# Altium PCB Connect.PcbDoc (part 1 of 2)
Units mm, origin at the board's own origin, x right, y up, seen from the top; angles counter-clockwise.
Board outline 480 x 50 mm, 2 copper layers (Top Layer, Bottom Layer); 349 components, 200 nets, 1147 pads, 734 vias.
Unrouted connection lines stored in the file: 1.
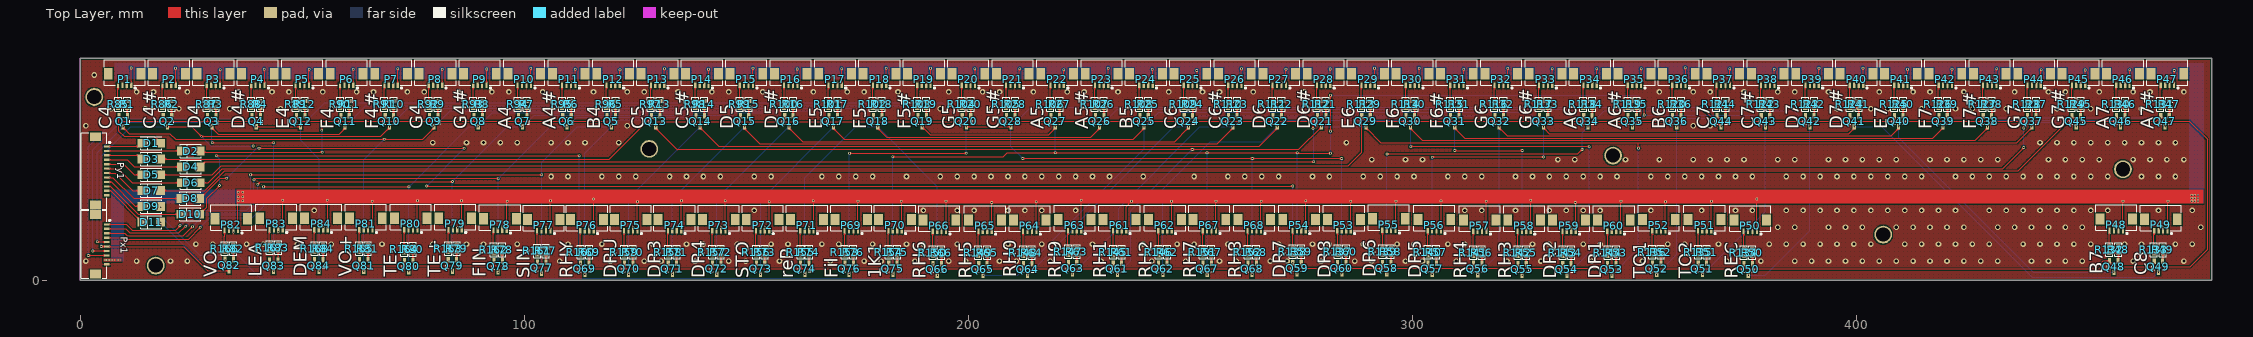
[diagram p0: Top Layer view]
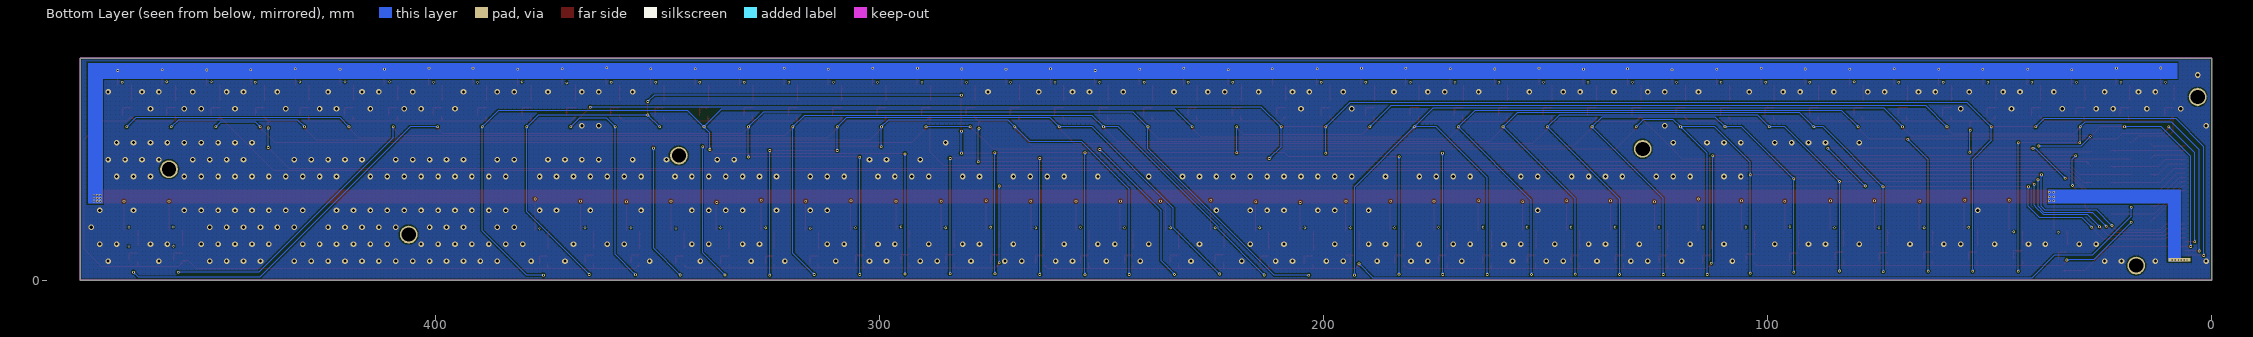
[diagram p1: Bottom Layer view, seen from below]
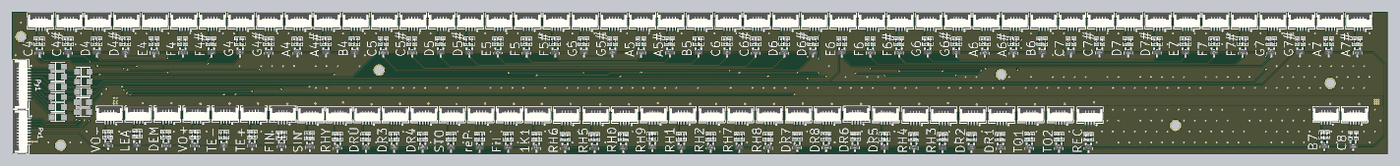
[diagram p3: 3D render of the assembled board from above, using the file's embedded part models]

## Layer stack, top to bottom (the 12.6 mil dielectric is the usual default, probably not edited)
Top Solder: solder mask 0.0102, Solder Resist, Dk 3.5
Top Layer: signal copper 0.0356
Dielectric 1: dielectric 0.32, FR-4, Dk 4.8
Bottom Layer: signal copper 0.0356
Bottom Solder: solder mask 0.0102, Solder Resist, Dk 3.5

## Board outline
0,0 0,50 480,50 480,0

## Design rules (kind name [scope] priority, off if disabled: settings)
Clearance [All] p1: gap=0.254
PolygonConnect [All] p1: connectstyle=Relief reliefconductorwidth=0.254 reliefentries=4 polygonreliefangle="90 Angle" airgapwidth=0.254
RoutingVias [All] p1: holewidth=0.3 width=0.6 viastyle="Through Hole" minholewidth=0.3 minwidth=0.6 maxholewidth=0.711 maxwidth=1.27
SolderMaskExpansion [All] p1: expansion=0.102
Width [All] p1: maxlimit=0.254 minlimit=0.254 preferedwidth=0.254
30 further rules are at their usual default settings.

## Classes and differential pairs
component class Sheet3: D1 D2 D3 D4 D5 D6 D7 D8 D9 D10 D11 Px1 Py1 Q1 Q2 Q3 Q4 Q5 Q6 Q7 Q8 Q9 Q10 Q11 Q12 Q13 Q14 Q15 Q16 Q17 Q18 Q19 Q20 Q21 Q22 Q23 Q24 Q25 Q26 Q27 Q28 Q29 Q30 Q31 Q32 Q33 Q34 Q35 Q36 Q37 Q38 Q39 Q40 Q41 Q42 Q43 Q44 Q45 Q46 Q47 Q48 Q49 Q50 Q51 Q52 Q53 Q54 Q55 Q56 Q57 Q58 Q59 Q60 Q61 Q62 Q63 Q64 Q65 Q66 Q67 Q68 Q69 Q70 Q71 Q72 Q73 Q74 Q75 Q76 Q77 Q79 Q80 Q81 Q82 Q83 Q84 R1 R2 R3 R4 R5 R6 R7 R8 R9 R10 R11 R12 R13 R14 R15 R16 R17 R18 R19 R20 R21 R22 R23 R24 R25 R26 R27 R28 R29 R30 R31 R32 R33 R34 R35 R36 R37 R38 R39 R40 R41 R42 R43 R44 R45 R46 R47 R48 R49 R50 R51 R52 R53 R54 R55 R56 R57 R58 R59 R60 R61 R62 R63 R64 R65 R66 R67 R68 R69 R70 R71 R72 R73 R74 R75 R76 R77 R79 R80 R81 R82 R83 R84
component class CONNECT: P21 P22 P23 P24 P25 P26 P27 P28 P29 P30 P31 P32 P33 P34 P35 P36 P37 P38 P39 P40 P41 P42 P43 P44 P45 P46 P47 P48 P49 P50 P51 P52 P53 P54 P55 P56 P57 P58 P59 P60 P61 P62 P63 P64 P65 P66 P67 P68 P69 P70 P71 P72 P73 P74 P75 P76 P77 P78 P79 P80 P81 P82 P83 P84 R105 R106 R107 R108 R109 R110 R111 R112 R113 R114 R115 R116 R117 R118 R119 R120 R121 R122 R123 R124 R125 R126 R127 R128 R129 R130 R131 R132 R133 R134 R135 R136 R137 R138 R139 R140 R141 R142 R143 R144 R145 R146 R147 R148 R149 R150 R151 R152 R153 R154 R155 R156 R157 R158 R159 R160 R161 R163 R164 R165 R166 R167 R168
component class CONNECT2: P1 P2 P3 P4 P5 P6 P7 P8 P9 P10 P11 P12 P13 P14 P15 P16 P17 P18 P19 P20 R85 R86 R87 R88 R89 R90 R91 R92 R93 R94 R95 R96 R97 R98 R99 R100 R101 R102 R103 R104

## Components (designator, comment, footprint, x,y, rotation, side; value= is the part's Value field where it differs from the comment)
D1 "M7" SMA(DO-214AC)_S1 16.002,30.861 r0 top
D2 "M7" SMA(DO-214AC)_S1 24.892,29.083 r0 top
D3 "M7" SMA(DO-214AC)_S1 16.002,27.305 r0 top
D4 "M7" SMA(DO-214AC)_S1 24.892,25.527 r0 top
D5 "M7" SMA(DO-214AC)_S1 16.002,23.749 r0 top
D6 "M7" SMA(DO-214AC)_S1 24.892,21.971 r0 top
D7 "M7" SMA(DO-214AC)_S1 16.002,20.193 r0 top
D8 "M7" SMA(DO-214AC)_S1 24.765,18.415 r0 top
D9 "M7" SMA(DO-214AC)_S1 16.002,16.637 r0 top
D10 "M7" SMA(DO-214AC)_S1 24.765,14.859 r0 top
D11 "M7" SMA(DO-214AC)_S1 16.002,13.081 r0 top
P1 "Header 4" FPC1.0-2H-WS-4P 10,46.5 r180 top
P2 "Header 4" FPC1.0-2H-WS-4P 20,46.5 r180 top
P3 "Header 4" FPC1.0-2H-WS-4P 30,46.5 r180 top
P4 "Header 4" FPC1.0-2H-WS-4P 40,46.5 r180 top
P5 "Header 4" FPC1.0-2H-WS-4P 50,46.5 r180 top
P6 "Header 4" FPC1.0-2H-WS-4P 60,46.5 r180 top
P7 "Header 4" FPC1.0-2H-WS-4P 70,46.5 r180 top
P8 "Header 4" FPC1.0-2H-WS-4P 80,46.5 r180 top
P9 "Header 4" FPC1.0-2H-WS-4P 90,46.5 r180 top
P10 "Header 4" FPC1.0-2H-WS-4P 100,46.5 r180 top
P11 "Header 4" FPC1.0-2H-WS-4P 110,46.5 r180 top
P12 "Header 4" FPC1.0-2H-WS-4P 120,46.5 r180 top
P13 "Header 4" FPC1.0-2H-WS-4P 130,46.5 r180 top
P14 "Header 4" FPC1.0-2H-WS-4P 140,46.5 r180 top
P15 "Header 4" FPC1.0-2H-WS-4P 150,46.5 r180 top
P16 "Header 4" FPC1.0-2H-WS-4P 160,46.5 r180 top
P17 "Header 4" FPC1.0-2H-WS-4P 170,46.5 r180 top
P18 "Header 4" FPC1.0-2H-WS-4P 180,46.5 r180 top
P19 "Header 4" FPC1.0-2H-WS-4P 190,46.5 r180 top
P20 "Header 4" FPC1.0-2H-WS-4P 200,46.5 r180 top
P21 "Header 4" FPC1.0-2H-WS-4P 210,46.5 r180 top
P22 "Header 4" FPC1.0-2H-WS-4P 220,46.5 r180 top
P23 "Header 4" FPC1.0-2H-WS-4P 230,46.5 r180 top
P24 "Header 4" FPC1.0-2H-WS-4P 240,46.5 r180 top
P25 "Header 4" FPC1.0-2H-WS-4P 250,46.5 r180 top
P26 "Header 4" FPC1.0-2H-WS-4P 260,46.5 r180 top
P27 "Header 4" FPC1.0-2H-WS-4P 270,46.5 r180 top
P28 "Header 4" FPC1.0-2H-WS-4P 280,46.5 r180 top
P29 "Header 4" FPC1.0-2H-WS-4P 290,46.5 r180 top
P30 "Header 4" FPC1.0-2H-WS-4P 300,46.5 r180 top
P31 "Header 4" FPC1.0-2H-WS-4P 310,46.5 r180 top
P32 "Header 4" FPC1.0-2H-WS-4P 320,46.5 r180 top
P33 "Header 4" FPC1.0-2H-WS-4P 330,46.5 r180 top
P34 "Header 4" FPC1.0-2H-WS-4P 340,46.5 r180 top
P35 "Header 4" FPC1.0-2H-WS-4P 350,46.5 r180 top
P36 "Header 4" FPC1.0-2H-WS-4P 360,46.5 r180 top
P37 "Header 4" FPC1.0-2H-WS-4P 370,46.5 r180 top
P38 "Header 4" FPC1.0-2H-WS-4P 380,46.5 r180 top
P39 "Header 4" FPC1.0-2H-WS-4P 390,46.5 r180 top
P40 "Header 4" FPC1.0-2H-WS-4P 400,46.5 r180 top
P41 "Header 4" FPC1.0-2H-WS-4P 410,46.5 r180 top
P42 "Header 4" FPC1.0-2H-WS-4P 420,46.5 r180 top
P43 "Header 4" FPC1.0-2H-WS-4P 430,46.5 r180 top
P44 "Header 4" FPC1.0-2H-WS-4P 440,46.5 r180 top
P45 "Header 4" FPC1.0-2H-WS-4P 450,46.5 r180 top
P46 "Header 4" FPC1.0-2H-WS-4P 460,46.5 r180 top
P47 "Header 4" FPC1.0-2H-WS-4P 470,46.5 r180 top
P48 "Header 4" FPC1.0-2H-WS-4P 458.494,13.777 r180 top
P49 "Header 4" FPC1.0-2H-WS-4P 468.537,13.734 r180 top
P50 "Header 4" FPC1.0-2H-WS-4P 376.081,13.589 r180 top
P51 "Header 4" FPC1.0-2H-WS-4P 365.777,13.716 r180 top
P52 "Header 4" FPC1.0-2H-WS-4P 355.481,13.716 r180 top
P53 "Header 4" FPC1.0-2H-WS-4P 284.586,13.716 r180 top
P54 "Header 4" FPC1.0-2H-WS-4P 274.476,13.716 r180 top
P55 "Header 4" FPC1.0-2H-WS-4P 294.695,13.843 r180 top
P56 "Header 4" FPC1.0-2H-WS-4P 304.932,13.716 r180 top
P57 "Header 4" FPC1.0-2H-WS-4P 315.169,13.589 r180 top
P58 "Header 4" FPC1.0-2H-WS-4P 325.152,13.589 r180 top
P59 "Header 4" FPC1.0-2H-WS-4P 335.261,13.589 r180 top
P60 "Header 4" FPC1.0-2H-WS-4P 345.371,13.589 r180 top
P61 "Header 4" FPC1.0-2H-WS-4P 234.037,13.716 r180 top
P62 "Header 4" FPC1.0-2H-WS-4P 244.274,13.716 r180 top
P63 "Header 4" FPC1.0-2H-WS-4P 223.928,13.716 r180 top
P64 "Header 4" FPC1.0-2H-WS-4P 213.818,13.589 r180 top
P65 "Header 4" FPC1.0-2H-WS-4P 203.754,13.589 r180 top
P66 "Header 4" FPC1.0-2H-WS-4P 193.472,13.589 r180 top
P67 "Header 4" FPC1.0-2H-WS-4P 254.257,13.716 r180 top
P68 "Header 4" FPC1.0-2H-WS-4P 264.366,13.716 r180 top
P69 "Header 4" FPC1.0-2H-WS-4P 173.633,13.716 r180 top
P70 "Header 4" FPC1.0-2H-WS-4P 183.489,13.716 r180 top
P71 "Header 4" FPC1.0-2H-WS-4P 163.651,13.716 r180 top
P72 "Header 4" FPC1.0-2H-WS-4P 153.668,13.716 r180 top
P73 "Header 4" FPC1.0-2H-WS-4P 143.812,13.716 r180 top
P74 "Header 4" FPC1.0-2H-WS-4P 133.83,13.716 r180 top
P75 "Header 4" FPC1.0-2H-WS-4P 123.974,13.716 r180 top
P76 "Header 4" FPC1.0-2H-WS-4P 114.118,13.716 r180 top
P77 "Header 4" FPC1.0-2H-WS-4P 104.39,13.716 r180 top
P78 "Header 4" FPC1.0-2H-WS-4P 94.534,13.843 r180 top
P79 "Header 4" FPC1.0-2H-WS-4P 84.424,13.97 r180 top
P80 "Header 4" FPC1.0-2H-WS-4P 74.442,13.97 r180 top
P81 "Header 4" FPC1.0-2H-WS-4P 64.332,13.97 r180 top
P82 "Header 4" FPC1.0-2H-WS-4P 34.003,13.843 r180 top
P83 "Header 4" FPC1.0-2H-WS-4P 44.113,13.97 r180 top
P84 "Header 4" FPC1.0-2H-WS-4P 54.222,13.97 r180 top
Px1 "Header 10" FPC1.0-2H-WS-10P 3.429,8.087 r270 top
Py1 "Header 12" FPC1.0-2H-WS-12P 3.429,24.638 r270 top
Q1 "SS8050 Y1" SOT-23(SOT-23-3) 9.652,35.814 r90 top
Q2 "SS8050 Y1" SOT-23(SOT-23-3) 19.648,35.814 r90 top
Q3 "SS8050 Y1" SOT-23(SOT-23-3) 29.644,35.814 r90 top
Q4 "SS8050 Y1" SOT-23(SOT-23-3) 39.64,35.814 r90 top
Q5 "SS8050 Y1" SOT-23(SOT-23-3) 119.608,35.814 r90 top
Q6 "SS8050 Y1" SOT-23(SOT-23-3) 109.612,35.814 r90 top
Q7 "SS8050 Y1" SOT-23(SOT-23-3) 99.616,35.814 r90 top
Q8 "SS8050 Y1" SOT-23(SOT-23-3) 89.62,35.814 r90 top
Q9 "SS8050 Y1" SOT-23(SOT-23-3) 79.624,35.814 r90 top
Q10 "SS8050 Y1" SOT-23(SOT-23-3) 69.628,35.814 r90 top
Q11 "SS8050 Y1" SOT-23(SOT-23-3) 59.632,35.814 r90 top
Q12 "SS8050 Y1" SOT-23(SOT-23-3) 49.636,35.814 r90 top
Q13 "SS8050 Y1" SOT-23(SOT-23-3) 129.603,35.814 r90 top
Q14 "SS8050 Y1" SOT-23(SOT-23-3) 139.599,35.814 r90 top
Q15 "SS8050 Y1" SOT-23(SOT-23-3) 149.595,35.814 r90 top
Q16 "SS8050 Y1" SOT-23(SOT-23-3) 159.591,35.814 r90 top
Q17 "SS8050 Y1" SOT-23(SOT-23-3) 169.587,35.814 r90 top
Q18 "SS8050 Y1" SOT-23(SOT-23-3) 179.583,35.814 r90 top
Q19 "SS8050 Y1" SOT-23(SOT-23-3) 189.579,35.814 r90 top
Q20 "SS8050 Y1" SOT-23(SOT-23-3) 199.575,35.814 r90 top
Q21 "SS8050 Y1" SOT-23(SOT-23-3) 279.543,35.814 r90 top
Q22 "SS8050 Y1" SOT-23(SOT-23-3) 269.547,35.814 r90 top
Q23 "SS8050 Y1" SOT-23(SOT-23-3) 259.551,35.814 r90 top
Q24 "SS8050 Y1" SOT-23(SOT-23-3) 249.555,35.814 r90 top
Q25 "SS8050 Y1" SOT-23(SOT-23-3) 239.559,35.814 r90 top
Q26 "SS8050 Y1" SOT-23(SOT-23-3) 229.563,35.814 r90 top
Q27 "SS8050 Y1" SOT-23(SOT-23-3) 219.567,35.814 r90 top
Q28 "SS8050 Y1" SOT-23(SOT-23-3) 209.571,35.814 r90 top
Q29 "SS8050 Y1" SOT-23(SOT-23-3) 289.539,35.814 r90 top
Q30 "SS8050 Y1" SOT-23(SOT-23-3) 299.535,35.814 r90 top
Q31 "SS8050 Y1" SOT-23(SOT-23-3) 309.531,35.814 r90 top
Q32 "SS8050 Y1" SOT-23(SOT-23-3) 319.527,35.814 r90 top
Q33 "SS8050 Y1" SOT-23(SOT-23-3) 329.523,35.814 r90 top
Q34 "SS8050 Y1" SOT-23(SOT-23-3) 339.519,35.814 r90 top
Q35 "SS8050 Y1" SOT-23(SOT-23-3) 349.515,35.814 r90 top
Q36 "SS8050 Y1" SOT-23(SOT-23-3) 359.51,35.814 r90 top
Q37 "SS8050 Y1" SOT-23(SOT-23-3) 439.478,35.814 r90 top
Q38 "SS8050 Y1" SOT-23(SOT-23-3) 429.482,35.814 r90 top
Q39 "SS8050 Y1" SOT-23(SOT-23-3) 419.486,35.814 r90 top
Q40 "SS8050 Y1" SOT-23(SOT-23-3) 409.49,35.814 r90 top
Q41 "SS8050 Y1" SOT-23(SOT-23-3) 399.494,35.814 r90 top
Q42 "SS8050 Y1" SOT-23(SOT-23-3) 389.498,35.814 r90 top
Q43 "SS8050 Y1" SOT-23(SOT-23-3) 379.502,35.814 r90 top
Q44 "SS8050 Y1" SOT-23(SOT-23-3) 369.506,35.814 r90 top
Q45 "SS8050 Y1" SOT-23(SOT-23-3) 449.474,35.814 r90 top
Q46 "SS8050 Y1" SOT-23(SOT-23-3) 459.47,35.814 r90 top
Q47 "SS8050 Y1" SOT-23(SOT-23-3) 469.466,35.814 r90 top
Q48 "SS8050 Y1" SOT-23(SOT-23-3) 457.956,3.091 r90 top
Q49 "SS8050 Y1" SOT-23(SOT-23-3) 467.995,3.048 r90 top
Q50 "SS8050 Y1" SOT-23(SOT-23-3) 375.614,2.433 r90 top
Q51 "SS8050 Y1" SOT-23(SOT-23-3) 365.31,2.56 r90 top
Q52 "SS8050 Y1" SOT-23(SOT-23-3) 355.013,2.56 r90 top
Q53 "SS8050 Y1" SOT-23(SOT-23-3) 344.903,2.433 r90 top
Q54 "SS8050 Y1" SOT-23(SOT-23-3) 334.793,2.433 r90 top
Q55 "SS8050 Y1" SOT-23(SOT-23-3) 324.683,2.433 r90 top
Q56 "SS8050 Y1" SOT-23(SOT-23-3) 314.706,2.54 r90 top
Q57 "SS8050 Y1" SOT-23(SOT-23-3) 304.463,2.56 r90 top
Q58 "SS8050 Y1" SOT-23(SOT-23-3) 294.226,2.687 r90 top
Q59 "SS8050 Y1" SOT-23(SOT-23-3) 274.007,2.687 r90 top
Q60 "SS8050 Y1" SOT-23(SOT-23-3) 284.117,2.687 r90 top
Q61 "SS8050 Y1" SOT-23(SOT-23-3) 233.567,2.56 r90 top
Q62 "SS8050 Y1" SOT-23(SOT-23-3) 243.804,2.56 r90 top
Q63 "SS8050 Y1" SOT-23(SOT-23-3) 223.457,2.687 r90 top
Q64 "SS8050 Y1" SOT-23(SOT-23-3) 213.347,2.433 r90 top
Q65 "SS8050 Y1" SOT-23(SOT-23-3) 203.283,2.433 r90 top
Q66 "SS8050 Y1" SOT-23(SOT-23-3) 193,2.433 r90 top
Q67 "SS8050 Y1" SOT-23(SOT-23-3) 253.787,2.56 r90 top
Q68 "SS8050 Y1" SOT-23(SOT-23-3) 263.897,2.56 r90 top
Q69 "SS8050 Y1" SOT-23(SOT-23-3) 113.645,2.56 r90 top
Q70 "SS8050 Y1" SOT-23(SOT-23-3) 123.501,2.56 r90 top
Q71 "SS8050 Y1" SOT-23(SOT-23-3) 133.357,2.56 r90 top
Q72 "SS8050 Y1" SOT-23(SOT-23-3) 143.34,2.56 r90 top
Q73 "SS8050 Y1" SOT-23(SOT-23-3) 153.196,2.56 r90 top
Q74 "SS8050 Y1" SOT-23(SOT-23-3) 163.179,2.56 r90 top
Q75 "SS8050 Y1" SOT-23(SOT-23-3) 183.018,2.56 r90 top
Q76 "SS8050 Y1" SOT-23(SOT-23-3) 173.162,2.56 r90 top
Q77 "SS8050 Y1" SOT-23(SOT-23-3) 103.916,2.814 r90 top
Q78 "SS8050 Y1" SOT-23(SOT-23-3) 94.107,3.155 r90 top
Q79 "SS8050 Y1" SOT-23(SOT-23-3) 83.824,3.322 r90 top
Q80 "SS8050 Y1" SOT-23(SOT-23-3) 73.968,3.195 r90 top
Q81 "SS8050 Y1" SOT-23(SOT-23-3) 63.858,3.322 r90 top
Q82 "SS8050 Y1" SOT-23(SOT-23-3) 33.528,3.429 r90 top
Q83 "SS8050 Y1" SOT-23(SOT-23-3) 43.561,3.282 r90 top
Q84 "SS8050 Y1" SOT-23(SOT-23-3) 53.748,3.322 r90 top
R1 "10KΩ (1002) ±1%" 0603_R 10.561,39.624 r270 top
R2 "10KΩ (1002) ±1%" 0603_R 20.559,39.624 r270 top
R3 "10KΩ (1002) ±1%" 0603_R 30.557,39.624 r270 top
R4 "10KΩ (1002) ±1%" 0603_R 40.556,39.624 r270 top
R5 "10KΩ (1002) ±1%" 0603_R 120.541,39.624 r270 top
R6 "10KΩ (1002) ±1%" 0603_R 110.543,39.624 r270 top
R7 "10KΩ (1002) ±1%" 0603_R 100.545,39.624 r270 top
R8 "10KΩ (1002) ±1%" 0603_R 90.547,39.624 r270 top
R9 "10KΩ (1002) ±1%" 0603_R 80.548,39.624 r270 top
R10 "10KΩ (1002) ±1%" 0603_R 70.55,39.624 r270 top
R11 "10KΩ (1002) ±1%" 0603_R 60.552,39.624 r270 top
R12 "10KΩ (1002) ±1%" 0603_R 50.554,39.624 r270 top
R13 "10KΩ (1002) ±1%" 0603_R 130.539,39.624 r270 top
R14 "10KΩ (1002) ±1%" 0603_R 140.537,39.624 r270 top
R15 "10KΩ (1002) ±1%" 0603_R 150.536,39.624 r270 top
R16 "10KΩ (1002) ±1%" 0603_R 160.534,39.624 r270 top
R17 "10KΩ (1002) ±1%" 0603_R 170.532,39.624 r270 top
R18 "10KΩ (1002) ±1%" 0603_R 180.53,39.624 r270 top
R19 "10KΩ (1002) ±1%" 0603_R 190.528,39.624 r270 top
R20 "10KΩ (1002) ±1%" 0603_R 200.527,39.624 r270 top
R21 "10KΩ (1002) ±1%" 0603_R 280.512,39.624 r270 top
R22 "10KΩ (1002) ±1%" 0603_R 270.514,39.624 r270 top
R23 "10KΩ (1002) ±1%" 0603_R 260.516,39.624 r270 top
R24 "10KΩ (1002) ±1%" 0603_R 250.518,39.624 r270 top
R25 "10KΩ (1002) ±1%" 0603_R 240.519,39.624 r270 top
R26 "10KΩ (1002) ±1%" 0603_R 230.521,39.624 r270 top
R27 "10KΩ (1002) ±1%" 0603_R 220.523,39.624 r270 top
R28 "10KΩ (1002) ±1%" 0603_R 210.525,39.624 r270 top
R29 "10KΩ (1002) ±1%" 0603_R 290.51,39.624 r270 top
R30 "10KΩ (1002) ±1%" 0603_R 300.508,39.624 r270 top
R31 "10KΩ (1002) ±1%" 0603_R 310.507,39.624 r270 top
R32 "10KΩ (1002) ±1%" 0603_R 320.505,39.624 r270 top
R33 "10KΩ (1002) ±1%" 0603_R 330.503,39.624 r270 top
R34 "10KΩ (1002) ±1%" 0603_R 340.501,39.624 r270 top
R35 "10KΩ (1002) ±1%" 0603_R 350.499,39.624 r270 top
R36 "10KΩ (1002) ±1%" 0603_R 360.498,39.624 r270 top
R37 "10KΩ (1002) ±1%" 0603_R 440.483,39.624 r270 top
R38 "10KΩ (1002) ±1%" 0603_R 430.485,39.624 r270 top
R39 "10KΩ (1002) ±1%" 0603_R 420.487,39.624 r270 top
R40 "10KΩ (1002) ±1%" 0603_R 410.489,39.624 r270 top
R41 "10KΩ (1002) ±1%" 0603_R 400.49,39.624 r270 top
R42 "10KΩ (1002) ±1%" 0603_R 390.492,39.624 r270 top
R43 "10KΩ (1002) ±1%" 0603_R 380.494,39.624 r270 top
R44 "10KΩ (1002) ±1%" 0603_R 370.496,39.624 r270 top
R45 "10KΩ (1002) ±1%" 0603_R 450.481,39.624 r270 top
R46 "10KΩ (1002) ±1%" 0603_R 460.479,39.624 r270 top
R47 "10KΩ (1002) ±1%" 0603_R 470.478,39.624 r270 top
R48 "10KΩ (1002) ±1%" 0603_R 458.97,6.901 r270 top
R49 "10KΩ (1002) ±1%" 0603_R 469.011,6.858 r270 top
R50 "10KΩ (1002) ±1%" 0603_R 376.555,6.223 r270 top
R51 "10KΩ (1002) ±1%" 0603_R 366.251,6.35 r270 top
R52 "10KΩ (1002) ±1%" 0603_R 355.953,6.35 r270 top
R53 "10KΩ (1002) ±1%" 0603_R 345.843,6.223 r270 top
R54 "10KΩ (1002) ±1%" 0603_R 335.732,6.223 r270 top
R55 "10KΩ (1002) ±1%" 0603_R 325.622,6.223 r270 top
R56 "10KΩ (1002) ±1%" 0603_R 315.639,6.223 r270 top
R57 "10KΩ (1002) ±1%" 0603_R 305.401,6.35 r270 top
R58 "10KΩ (1002) ±1%" 0603_R 295.164,6.477 r270 top
R59 "10KΩ (1002) ±1%" 0603_R 274.943,6.477 r270 top
R60 "10KΩ (1002) ±1%" 0603_R 285.054,6.477 r270 top
R61 "10KΩ (1002) ±1%" 0603_R 234.502,6.35 r270 top
R62 "10KΩ (1002) ±1%" 0603_R 244.739,6.35 r270 top
R63 "10KΩ (1002) ±1%" 0603_R 224.391,6.477 r270 top
R64 "10KΩ (1002) ±1%" 0603_R 214.281,6.223 r270 top
R65 "10KΩ (1002) ±1%" 0603_R 204.216,6.223 r270 top
R66 "10KΩ (1002) ±1%" 0603_R 193.933,6.223 r270 top
R67 "10KΩ (1002) ±1%" 0603_R 254.723,6.35 r270 top
R68 "10KΩ (1002) ±1%" 0603_R 264.833,6.35 r270 top
R69 "10KΩ (1002) ±1%" 0603_R 114.574,6.35 r270 top
R70 "10KΩ (1002) ±1%" 0603_R 124.431,6.35 r270 top
R71 "10KΩ (1002) ±1%" 0603_R 134.287,6.35 r270 top
R72 "10KΩ (1002) ±1%" 0603_R 144.271,6.35 r270 top
R73 "10KΩ (1002) ±1%" 0603_R 154.127,6.35 r270 top
R74 "10KΩ (1002) ±1%" 0603_R 164.11,6.35 r270 top
R75 "10KΩ (1002) ±1%" 0603_R 183.95,6.35 r270 top
R76 "10KΩ (1002) ±1%" 0603_R 174.094,6.35 r270 top
R77 "10KΩ (1002) ±1%" 0603_R 104.845,6.604 r270 top
R78 "10KΩ (1002) ±1%" 0603_R 94.989,6.858 r270 top
R79 "10KΩ (1002) ±1%" 0603_R 84.751,7.112 r270 top
R80 "10KΩ (1002) ±1%" 0603_R 74.895,6.985 r270 top
R81 "10KΩ (1002) ±1%" 0603_R 64.785,7.112 r270 top
R82 "10KΩ (1002) ±1%" 0603_R 34.454,7.112 r270 top
R83 "10KΩ (1002) ±1%" 0603_R 44.564,7.366 r270 top
R84 "10KΩ (1002) ±1%" 0603_R 54.674,7.112 r270 top
R85 "1KΩ (1001) ±1%" 0603_R 8.509,39.624 r90 top
R86 "1KΩ (1001) ±1%" 0603_R 18.508,39.624 r90 top
R87 "1KΩ (1001) ±1%" 0603_R 28.506,39.624 r90 top
R88 "1KΩ (1001) ±1%" 0603_R 38.505,39.624 r90 top
R89 "1KΩ (1001) ±1%" 0603_R 48.503,39.624 r90 top
R90 "1KΩ (1001) ±1%" 0603_R 58.502,39.624 r90 top
R91 "1KΩ (1001) ±1%" 0603_R 68.501,39.624 r90 top
R92 "1KΩ (1001) ±1%" 0603_R 78.499,39.624 r90 top
R93 "1KΩ (1001) ±1%" 0603_R 88.498,39.624 r90 top
R94 "1KΩ (1001) ±1%" 0603_R 98.496,39.624 r90 top
R95 "1KΩ (1001) ±1%" 0603_R 108.495,39.624 r90 top
R96 "1KΩ (1001) ±1%" 0603_R 118.494,39.624 r90 top
R97 "1KΩ (1001) ±1%" 0603_R 128.492,39.624 r90 top
R98 "1KΩ (1001) ±1%" 0603_R 138.491,39.624 r90 top
R99 "1KΩ (1001) ±1%" 0603_R 148.489,39.624 r90 top
R100 "1KΩ (1001) ±1%" 0603_R 158.488,39.624 r90 top
R101 "1KΩ (1001) ±1%" 0603_R 168.487,39.624 r90 top
R102 "1KΩ (1001) ±1%" 0603_R 178.485,39.624 r90 top
R103 "1KΩ (1001) ±1%" 0603_R 188.484,39.624 r90 top
R104 "1KΩ (1001) ±1%" 0603_R 198.482,39.624 r90 top
R105 "1KΩ (1001) ±1%" 0603_R 208.481,39.624 r90 top
R106 "1KΩ (1001) ±1%" 0603_R 218.48,39.624 r90 top
R107 "1KΩ (1001) ±1%" 0603_R 228.478,39.624 r90 top
R108 "1KΩ (1001) ±1%" 0603_R 238.477,39.624 r90 top
R109 "1KΩ (1001) ±1%" 0603_R 248.475,39.624 r90 top
R110 "1KΩ (1001) ±1%" 0603_R 258.474,39.624 r90 top
R111 "1KΩ (1001) ±1%" 0603_R 268.473,39.624 r90 top
R112 "1KΩ (1001) ±1%" 0603_R 278.471,39.624 r90 top
R113 "1KΩ (1001) ±1%" 0603_R 288.47,39.624 r90 top
R114 "1KΩ (1001) ±1%" 0603_R 298.468,39.624 r90 top
R115 "1KΩ (1001) ±1%" 0603_R 308.467,39.624 r90 top
R116 "1KΩ (1001) ±1%" 0603_R 318.466,39.624 r90 top
R117 "1KΩ (1001) ±1%" 0603_R 328.464,39.624 r90 top
R118 "1KΩ (1001) ±1%" 0603_R 338.463,39.624 r90 top
R119 "1KΩ (1001) ±1%" 0603_R 348.462,39.624 r90 top
R120 "1KΩ (1001) ±1%" 0603_R 358.46,39.624 r90 top
R121 "1KΩ (1001) ±1%" 0603_R 368.459,39.624 r90 top
R122 "1KΩ (1001) ±1%" 0603_R 378.457,39.624 r90 top
R123 "1KΩ (1001) ±1%" 0603_R 388.456,39.624 r90 top
R124 "1KΩ (1001) ±1%" 0603_R 398.455,39.624 r90 top
R125 "1KΩ (1001) ±1%" 0603_R 408.453,39.624 r90 top
R126 "1KΩ (1001) ±1%" 0603_R 418.452,39.624 r90 top
R127 "1KΩ (1001) ±1%" 0603_R 428.45,39.624 r90 top
R128 "1KΩ (1001) ±1%" 0603_R 438.449,39.624 r90 top
R129 "1KΩ (1001) ±1%" 0603_R 448.448,39.624 r90 top
R130 "1KΩ (1001) ±1%" 0603_R 458.446,39.624 r90 top
R131 "1KΩ (1001) ±1%" 0603_R 468.445,39.624 r90 top
R132 "1KΩ (1001) ±1%" 0603_R 456.937,6.901 r90 top
R133 "1KΩ (1001) ±1%" 0603_R 466.979,6.858 r90 top
R134 "1KΩ (1001) ±1%" 0603_R 374.65,6.223 r90 top
R135 "1KΩ (1001) ±1%" 0603_R 364.345,6.35 r90 top
R136 "1KΩ (1001) ±1%" 0603_R 354.048,6.35 r90 top
R137 "1KΩ (1001) ±1%" 0603_R 283.149,6.477 r90 top
R138 "1KΩ (1001) ±1%" 0603_R 273.038,6.477 r90 top
R139 "1KΩ (1001) ±1%" 0603_R 293.259,6.477 r90 top
R140 "1KΩ (1001) ±1%" 0603_R 303.496,6.35 r90 top
R141 "1KΩ (1001) ±1%" 0603_R 313.734,6.223 r90 top
R142 "1KΩ (1001) ±1%" 0603_R 323.717,6.223 r90 top
R143 "1KΩ (1001) ±1%" 0603_R 333.827,6.223 r90 top
R144 "1KΩ (1001) ±1%" 0603_R 343.938,6.223 r90 top
R145 "1KΩ (1001) ±1%" 0603_R 232.597,6.35 r90 top
R146 "1KΩ (1001) ±1%" 0603_R 242.834,6.35 r90 top
R147 "1KΩ (1001) ±1%" 0603_R 222.486,6.477 r90 top
R148 "1KΩ (1001) ±1%" 0603_R 212.376,6.223 r90 top
R149 "1KΩ (1001) ±1%" 0603_R 202.184,6.223 r90 top
R150 "1KΩ (1001) ±1%" 0603_R 192.028,6.223 r90 top
R151 "1KΩ (1001) ±1%" 0603_R 252.817,6.35 r90 top
R152 "1KΩ (1001) ±1%" 0603_R 262.928,6.35 r90 top
R153 "1KΩ (1001) ±1%" 0603_R 172.189,6.35 r90 top
R154 "1KΩ (1001) ±1%" 0603_R 182.045,6.35 r90 top
R155 "1KΩ (1001) ±1%" 0603_R 162.205,6.35 r90 top
R156 "1KΩ (1001) ±1%" 0603_R 152.222,6.35 r90 top
R157 "1KΩ (1001) ±1%" 0603_R 142.365,6.35 r90 top
R158 "1KΩ (1001) ±1%" 0603_R 132.382,6.35 r90 top
R159 "1KΩ (1001) ±1%" 0603_R 122.526,6.35 r90 top
R160 "1KΩ (1001) ±1%" 0603_R 112.669,6.35 r90 top
R161 "1KΩ (1001) ±1%" 0603_R 102.94,6.604 r90 top
R162 "1KΩ (1001) ±1%" 0603_R 93.084,6.858 r90 top
R163 "1KΩ (1001) ±1%" 0603_R 82.846,7.112 r90 top
R164 "1KΩ (1001) ±1%" 0603_R 72.99,6.985 r90 top
R165 "1KΩ (1001) ±1%" 0603_R 62.88,7.112 r90 top
R166 "1KΩ (1001) ±1%" 0603_R 32.549,7.112 r90 top
R167 "1KΩ (1001) ±1%" 0603_R 42.659,7.366 r90 top
R168 "1KΩ (1001) ±1%" 0603_R 52.769,7.112 r90 top

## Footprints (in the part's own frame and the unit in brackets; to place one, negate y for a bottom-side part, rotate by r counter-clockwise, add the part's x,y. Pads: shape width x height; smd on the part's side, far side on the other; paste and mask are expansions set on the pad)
0603_R [mm]
  rect 0.93x0.98 smd: 1(-0.77,0) 2(0.77,0)
  silkscreen extent -1.54,-0.79 1.54,0.79, body extent -0.85,-0.4 0.85,0.4, height 0.56
FPC1.0-2H-WS-4P [mm] "翻盖FPC，脚距1mm，不含脚（长8.9mm，宽5.2mm，高1.96mm）"
  rect 2x2.5 smd: 0(-3.69,0) 0(3.69,0)
  rect 0.5x1.25 smd: 1(-1.5,2.575) 2(-0.5,2.575) 3(0.5,2.575) 4(1.5,2.575)
  silkscreen extent -4.64,-3.17 4.64,3.31, body extent -4.45,-3.15 4.45,2.85, height 2
FPC1.0-2H-WS-10P [mm] "翻盖FPC，脚距1mm，不含脚（长14.9mm，宽5.2mm，高1.96mm）"
  rect 2x2.5 smd: 0(-6.69,0) 0(6.69,0)
  rect 0.5x1.25 smd: 1(-4.5,2.575) 2(-3.5,2.575) 3(-2.5,2.575) 4(-1.5,2.575) 5(-0.5,2.575) 6(0.5,2.575) 7(1.5,2.575) 8(2.5,2.575) 9(3.5,2.575) 10(4.5,2.575)
  silkscreen extent -7.64,-3.18 7.64,3.31, body extent -7.45,-3.15 7.45,2.85, height 2
FPC1.0-2H-WS-12P [mm] "翻盖FPC，脚距1mm，不含脚（长16.9mm，宽5.2mm，高1.96mm）"
  rect 2x2.5 smd: 0(-7.69,0) 0(7.69,0)
  rect 0.5x1.25 smd: 1(-5.5,2.575) 2(-4.5,2.575) 3(-3.5,2.575) 4(-2.5,2.575) 5(-1.5,2.575) 6(-0.5,2.575) 7(0.5,2.575) 8(1.5,2.575) 9(2.5,2.575) 10(3.5,2.575) 11(4.5,2.575) 12(5.5,2.575)
  silkscreen extent -8.64,-3.18 8.64,3.31, body extent -8.45,-3.15 8.45,2.85, height 2
SMA(DO-214AC)_S1 [mm]
  rect 2x2 smd: 1(2.1,0) 2(-2.1,0)
  silkscreen extent -2.35,-1.5 2.35,1.5
SOT-23(SOT-23-3) [mm]
  rect 1.25x0.7 smd: 1(1.25,-0.95) 2(1.25,0.95) 3(-1.25,0)
  silkscreen extent -0.65,-1.46 0.9,1.46, body extent -1.5,-1.5 1.5,1.5, height 1.3

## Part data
D1 D2 D3 D4 D5 D6 D7 D8 D9 D10 D11: library part "SMA(DO-214AC) M7", "二极管"
P1 P2 P3 P4 P5 P6 P7 P8 P9 P10 P11 P12 P13 P14 P15 P16 P17 P18 P19 P20 P21 P22 P23 P24 P25 P26 P27 P28 P29 P30 P31 P32 P33 P34 P35 P36 P37 P38 P39 P40 P41 P42 P43 P44 P45 P46 P47 P48 P49 P50 P51 P52 P53 P54 P55 P56 P57 P58 P59 P60 P61 P62 P63 P64 P65 P66 P67 P68 P69 P70 P71 P72 P73 P74 P75 P76 P77 P78 P79 P80 P81 P82 P83 P84: "Header, 4-Pin"
Px1: "Header, 10-Pin"
Py1: "Header, 12-Pin"
Q1 Q2 Q3 Q4 Q5 Q6 Q7 Q8 Q9 Q10 Q11 Q12 Q13 Q14 Q15 Q16 Q17 Q18 Q19 Q20 Q21 Q22 Q23 Q24 Q25 Q26 Q27 Q28 Q29 Q30 Q31 Q32 Q33 Q34 Q35 Q36 Q37 Q38 Q39 Q40 Q41 Q42 Q43 Q44 Q45 Q46 Q47 Q48 Q49 Q50 Q51 Q52 Q53 Q54 Q55 Q56 Q57 Q58 Q59 Q60 Q61 Q62 Q63 Q64 Q65 Q66 Q67 Q68 Q69 Q70 Q71 Q72 Q73 Q74 Q75 Q76 Q77 Q78 Q79 Q80 Q81 Q82 Q83 Q84: library part "SOT-23 SS8050 Y1", "三极管"
R1 R2 R3 R4 R5 R6 R7 R8 R9 R10 R11 R12 R13 R14 R15 R16 R17 R18 R19 R20 R21 R22 R23 R24 R25 R26 R27 R28 R29 R30 R31 R32 R33 R34 R35 R36 R37 R38 R39 R40 R41 R42 R43 R44 R45 R46 R47 R48 R49 R50 R51 R52 R53 R54 R55 R56 R57 R58 R59 R60 R61 R62 R63 R64 R65 R66 R67 R68 R69 R70 R71 R72 R73 R74 R75 R76 R77 R78 R79 R80 R81 R82 R83 R84: library part "0603 10KΩ (1002) 1%", "贴片电阻"
R85 R86 R87 R88 R89 R90 R91 R92 R93 R94 R95 R96 R97 R98 R99 R100 R101 R102 R103 R104 R105 R106 R107 R108 R109 R110 R111 R112 R113 R114 R115 R116 R117 R118 R119 R120 R121 R122 R123 R124 R125 R126 R127 R128 R129 R130 R131 R132 R133 R134 R135 R136 R137 R138 R139 R140 R141 R142 R143 R144 R145 R146 R147 R148 R149 R150 R151 R152 R153 R154 R155 R156 R157 R158 R159 R160 R161 R162 R163 R164 R165 R166 R167 R168: library part "0603 1KΩ (1001) 1%", "贴片电阻"

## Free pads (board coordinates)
  round 4 hole 3.2: 0(3.175,41.275) 0(17.018,3.302) 0(128.143,29.591) 0(345.186,28.067) 0(406.019,10.287) 0(460,25)
  rect 5x0.8 smd far side: 2(7.239,4.572)

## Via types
v1: diameter 1.27, hole 0.711, Top Layer to Bottom Layer, tented both sides, 396 vias
v2: diameter 0.6, hole 0.3, Top Layer to Bottom Layer, 231 vias
v3: diameter 0.5, hole 0.3, Top Layer to Bottom Layer, 107 vias

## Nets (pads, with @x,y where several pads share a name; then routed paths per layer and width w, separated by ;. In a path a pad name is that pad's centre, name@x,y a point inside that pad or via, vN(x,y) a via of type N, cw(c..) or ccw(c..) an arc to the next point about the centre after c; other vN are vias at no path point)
1K1N: Q75.1 R75.2 R154.1 | length 3.7
  Top Layer w0.254: R154.1@182.045,5.58 R75.2@183.95,5.58 183.968,5.58 Q75.1@183.968,3.81
A4: Q7.1 R7.2 R94.1 | length 3.8
  Top Layer w0.254: R94.1@98.496,38.854 R7.2@100.545,38.854 100.545,37.085 Q7.1@100.566,37.064
A4#: Q6.1 R6.2 R95.1 | length 3.8
  Top Layer w0.254: R95.1@108.495,38.854 R6.2@110.543,38.854 110.543,37.083 Q6.1@110.562,37.064
A5: Q27.1 R27.2 R106.1 | length 3.8
  Top Layer w0.254: R106.1@218.48,38.854 R27.2@220.523,38.854 220.523,37.07 Q27.1@220.517,37.064
A5#: Q26.1 R26.2 R107.1 | length 3.8
  Top Layer w0.254: R107.1@228.478,38.854 R26.2@230.521,38.854 230.521,37.072 Q26.1@230.513,37.064
A6: Q34.1 R34.2 R118.1 | length 3.8
  Top Layer w0.254: R118.1@338.463,38.854 R34.2@340.501,38.854 340.501,37.097 Q34.1@340.469,37.064
A6#: Q35.1 R35.2 R119.1 | length 3.8
  Top Layer w0.254: R119.1@348.462,38.854 R35.2@350.499,38.854 350.499,37.099 Q35.1@350.465,37.064
A7: Q46.1 R46.2 R130.1 | length 3.8
  Top Layer w0.254: R130.1@458.446,38.854 R46.2@460.479,38.854 460.479,37.123 Q46.1@460.42,37.064
A7#: Q47.1 R47.2 R131.1 | length 3.8
  Top Layer w0.254: R131.1@468.445,38.854 R47.2@470.478,38.854 470.478,37.126 Q47.1@470.416,37.064
B4: Q5.1 R5.2 R96.1 | length 3.8
  Top Layer w0.254: R96.1@118.494,38.854 R5.2@120.541,38.854 120.541,37.08 Q5.1@120.558,37.064
B5: Q25.1 R25.2 R108.1 | length 3.8
  Top Layer w0.254: R108.1@238.477,38.854 R25.2@240.519,38.854 240.519,37.074 Q25.1@240.509,37.064
B6: Q36.1 R36.2 R120.1 | length 3.8
  Top Layer w0.254: R120.1@358.46,38.854 R36.2@360.498,38.854 360.498,37.101 Q36.1@360.46,37.064
B7: Q48.1 R48.2 R132.1 | length 3.8
  Top Layer w0.254: R132.1@456.937,6.131 R48.2@458.97,6.131 458.97,4.405 Q48.1@458.906,4.341
C4: Q1.1 R1.2 R85.1 | length 3.9
  Top Layer w0.254: R85.1@8.509,38.854 R1.2@10.561,38.854 10.561,37.105 Q1.1@10.602,37.064
C4#: Q2.1 R2.2 R86.1 | length 3.9
  Top Layer w0.254: R86.1@18.508,38.854 R2.2@20.559,38.854 20.559,37.103 Q2.1@20.598,37.064
C5: Q13.1 R13.2 R97.1 | length 3.8
  Top Layer w0.254: R97.1@128.492,38.854 R13.2@130.539,38.854 130.539,37.078 Q13.1@130.553,37.064
C5#: Q14.1 R14.2 R98.1 | length 3.8
  Top Layer w0.254: R98.1@138.491,38.854 R14.2@140.537,38.854 140.537,37.076 Q14.1@140.549,37.064
C6: Q24.1 R24.2 R109.1 | length 3.8
  Top Layer w0.254: R109.1@248.475,38.854 R24.2@250.518,38.854 250.518,37.077 Q24.1@250.505,37.064
C6#: Q23.1 R23.2 R110.1 | length 3.8
  Top Layer w0.254: R110.1@258.474,38.854 R23.2@260.516,38.854 260.516,37.079 Q23.1@260.501,37.064
C7: Q44.1 R44.2 R121.1 | length 3.8
  Top Layer w0.254: R121.1@368.459,38.854 R44.2@370.496,38.854 370.496,37.103 Q44.1@370.456,37.064
C7#: Q43.1 R43.2 R122.1 | length 3.8
  Top Layer w0.254: R122.1@378.457,38.854 R43.2@380.494,38.854 ; Q43.1@380.452,37.064 380.494,37.106 R43.2@380.494,38.854
C8: Q49.1 R49.2 R133.1 | length 3.8
  Top Layer w0.254: R133.1@466.979,6.088 R49.2@469.011,6.088 469.011,4.364 Q49.1@468.945,4.298
D4: Q3.1 R3.2 R87.1 | length 3.9
  Top Layer w0.254: R87.1@28.506,38.854 R3.2@30.557,38.854 30.557,37.101 Q3.1@30.594,37.064
D4#: Q4.1 R4.2 R88.1 | length 3.9
  Top Layer w0.254: R88.1@38.505,38.854 R4.2@40.556,38.854 40.556,37.098 Q4.1@40.59,37.064
D5: Q15.1 R15.2 R99.1 | length 3.8
  Top Layer w0.254: R99.1@148.489,38.854 R15.2@150.536,38.854 150.536,37.074 Q15.1@150.545,37.064
D5#: Q16.1 R16.2 R100.1 | length 3.8
  Top Layer w0.254: R100.1@158.488,38.854 R16.2@160.534,38.854 160.534,37.072 Q16.1@160.541,37.064
D6: Q22.1 R22.2 R111.1 | length 3.8
  Top Layer w0.254: R111.1@268.473,38.854 R22.2@270.514,38.854 270.514,37.081 Q22.1@270.497,37.064
D6#: Q21.1 R21.2 R112.1 | length 3.8
  Top Layer w0.254: R112.1@278.471,38.854 R21.2@280.512,38.854 280.512,37.083 Q21.1@280.493,37.064
D7: Q42.1 R42.2 R123.1 | length 3.8
  Top Layer w0.254: R123.1@388.456,38.854 R42.2@390.492,38.854 390.492,37.108 Q42.1@390.448,37.064
D7#: Q41.1 R41.2 R124.1 | length 3.8
  Top Layer w0.254: R124.1@398.455,38.854 R41.2@400.49,38.854 400.49,37.11 Q41.1@400.444,37.064
DEMO: Q84.1 R84.2 R168.1 | length 3.7
  Top Layer w0.254: R168.1@52.769,6.342 53.721,6.342 R84.2@54.674,6.342 54.674,5.588 54.698,5.565 Q84.1@54.698,4.572
DR1: Q53.1 R53.2 R144.1 | length 3.7
  Top Layer w0.254: R144.1@343.938,5.453 R53.2@345.843,5.453 345.843,3.693 Q53.1@345.853,3.683
DR2: Q54.1 R54.2 R143.1 | length 3.7
  Top Layer w0.254: R143.1@333.827,5.453 R54.2@335.732,5.453 335.732,3.694 Q54.1@335.743,3.683
DR3: Q71.1 R71.2 R158.1 | length 3.7
  Top Layer w0.254: R158.1@132.382,5.58 R71.2@134.287,5.58 134.307,5.58 Q71.1@134.307,3.81
DR4: Q72.1 R72.2 R157.1 | length 3.7
  Top Layer w0.254: R157.1@142.365,5.58 R72.2@144.271,5.58 144.29,5.58 Q72.1@144.29,3.81
DR5: Q57.1 R57.2 R140.1 | length 3.7
  Top Layer w0.254: R140.1@303.496,5.58 R57.2@305.401,5.58 305.401,3.822 Q57.1@305.413,3.81
DR6: Q58.1 R58.2 R139.1 | length 3.7
  Top Layer w0.254: R139.1@293.259,5.707 R58.2@295.164,5.707 295.164,3.949 Q58.1@295.176,3.937
DR7: Q59.1 R59.2 R138.1 | length 3.7
  Top Layer w0.254: R138.1@273.038,5.707 R59.2@274.943,5.707 274.943,3.95 Q59.1@274.957,3.937
DR8: Q60.1 R60.2 R137.1 | length 3.7
  Top Layer w0.254: R137.1@283.149,5.707 R60.2@285.054,5.707 285.054,3.95 Q60.1@285.067,3.937
DRUM: Q70.1 R70.2 R159.1 | length 3.7
  Top Layer w0.254: R159.1@122.526,5.58 R70.2@124.431,5.58 124.451,5.58 Q70.1@124.451,3.81
E4: Q12.1 R12.2 R89.1 | length 3.9
  Top Layer w0.254: R89.1@48.503,38.854 R12.2@50.554,38.854 50.554,37.096 Q12.1@50.586,37.064
E5: Q17.1 R17.2 R101.1 | length 3.8
  Top Layer w0.254: R101.1@168.487,38.854 R17.2@170.532,38.854 170.532,37.069 Q17.1@170.537,37.064
E6: Q29.1 R29.2 R113.1 | length 3.8
  Top Layer w0.254: R113.1@288.47,38.854 R29.2@290.51,38.854 290.51,37.085 Q29.1@290.489,37.064
E7: Q40.1 R40.2 R125.1 | length 3.8
  Top Layer w0.254: R125.1@408.453,38.854 R40.2@410.488,38.854 410.488,37.112 Q40.1@410.44,37.064
F4: Q11.1 R11.2 R90.1 | length 3.9
  Top Layer w0.254: R90.1@58.502,38.854 R11.2@60.552,38.854 60.552,37.094 Q11.1@60.582,37.064
F4#: Q10.1 R10.2 R91.1 | length 3.9
  Top Layer w0.254: R91.1@68.501,38.854 R10.2@70.55,38.854 70.55,37.092 Q10.1@70.578,37.064
F5: Q18.1 R18.2 R102.1 | length 3.8
  Top Layer w0.254: R102.1@178.485,38.854 R18.2@180.53,38.854 180.53,37.067 Q18.1@180.533,37.064
F5#: Q19.1 R19.2 R103.1 | length 3.8
  Top Layer w0.254: R103.1@188.484,38.854 R19.2@190.528,38.854 Q19.1@190.528,37.065
F6: Q30.1 R30.2 R114.1 | length 3.8
  Top Layer w0.254: R114.1@298.468,38.854 R30.2@300.508,38.854 300.508,37.088 Q30.1@300.485,37.064
F6#: Q31.1 R31.2 R115.1 | length 3.8
  Top Layer w0.254: R115.1@308.467,38.854 R31.2@310.507,38.854 310.507,37.09 Q31.1@310.481,37.064
F7: Q39.1 R39.2 R126.1 | length 3.8
  Top Layer w0.254: R126.1@418.452,38.854 R39.2@420.487,38.854 420.487,37.114 Q39.1@420.436,37.064
F7#: Q38.1 R38.2 R127.1 | length 3.8
  Top Layer w0.254: R127.1@428.45,38.854 R38.2@430.485,38.854 430.485,37.117 Q38.1@430.432,37.064
FILLIN: Q76.1 R76.2 R153.1 | length 3.7
  Top Layer w0.254: R153.1@172.189,5.58 R76.2@174.094,5.58 174.112,5.58 Q76.1@174.112,3.81
FINGER: Q78.1 R78.2 R162.1 | length 3.7
  Top Layer w0.254: R162.1@93.084,6.088 R78.2@94.989,6.088 95.01,6.088 Q78.1@95.01,4.318
G4: Q9.1 R9.2 R92.1 | length 3.8
  Top Layer w0.254: R92.1@78.499,38.854 R9.2@80.548,38.854 80.548,37.089 Q9.1@80.574,37.064
G4#: Q8.1 R8.2 R93.1 | length 3.8
  Top Layer w0.254: R93.1@88.498,38.854 R8.2@90.547,38.854 90.547,37.087 Q8.1@90.57,37.064
G5: Q20.1 R20.2 R104.1 | length 3.8
  Top Layer w0.254: R104.1@198.482,38.854 R20.2@200.527,38.854 200.527,37.065 Q20.1@200.525,37.064
G5#: Q28.1 R28.2 R105.1 | length 3.8
  Top Layer w0.254: R105.1@208.481,38.854 R28.2@210.525,38.854 ; Q28.1@210.521,37.064 210.525,37.068 R28.2@210.525,38.854
G6: Q32.1 R32.2 R116.1 | length 3.8
  Top Layer w0.254: R116.1@318.466,38.854 R32.2@320.505,38.854 320.505,37.092 Q32.1@320.477,37.064
G6#: Q33.1 R33.2 R117.1 | length 3.8
  Top Layer w0.254: R117.1@328.464,38.854 R33.2@330.503,38.854 330.503,37.094 Q33.1@330.473,37.064
G7: Q37.1 R37.2 R128.1 | length 3.8
  Top Layer w0.254: R128.1@438.449,38.854 R37.2@440.483,38.854 440.428,38.799 Q37.1@440.428,37.064
G7#: Q45.1 R45.2 R129.1 | length 3.8
  Top Layer w0.254: R129.1@448.448,38.854 R45.2@450.481,38.854 450.481,37.121 Q45.1@450.424,37.064
GND: P1.2 P2.2 P3.2 P4.2 P5.2 P6.2 P7.2 P8.2 P9.2 P10.2 P11.2 P12.2 P13.2 P14.2 P15.2 P16.2 P17.2 P18.2 P19.2 P20.2 P21.2 P22.2 P23.2 P24.2 P25.2 P26.2 P27.2 P28.2 P29.2 P30.2 P31.2 P32.2 P33.2 P34.2 P35.2 P36.2 P37.2 P38.2 P39.2 P40.2 P41.2 P42.2 P43.2 P44.2 P45.2 P46.2 P47.2 P48.2 P49.2 P50.2 P51.2 P52.2 P53.2 P54.2 P55.2 P56.2 P57.2 P58.2 P59.2 P60.2 P61.2 P62.2 P63.2 P64.2 P65.2 P66.2 P67.2 P68.2 P69.2 P70.2 P71.2 P72.2 P73.2 P74.2 P75.2 P76.2 P77.2 P78.2 P79.2 P80.2 P81.2 P82.2 P83.2 P84.2 pad.0@3.175,41.275 Px1.10 R1.1 R2.1 R3.1 R4.1 R5.1 R6.1 R7.1 R8.1 R9.1 R10.1 R11.1 R12.1 R13.1 R14.1 R15.1 R16.1 R17.1 R18.1 R19.1 R20.1 R21.1 R22.1 R23.1 R24.1 R25.1 R26.1 R27.1 R28.1 R29.1 R30.1 R31.1 R32.1 R33.1 R34.1 R35.1 R36.1 R37.1 R38.1 R39.1 R40.1 R41.1 R42.1 R43.1 R44.1 R45.1 R46.1 R47.1 R48.1 R49.1 R50.1 R51.1 R52.1 R53.1 R54.1 R55.1 R56.1 R57.1 R58.1 R59.1 R60.1 R61.1 R62.1 R63.1 R64.1 R65.1 R66.1 R67.1 R68.1 R69.1 R70.1 R71.1 R72.1 R73.1 R74.1 R75.1 R76.1 R77.1 R78.1 R79.1 R80.1 R81.1 R82.1 R83.1 R84.1
  other v1: 1.27,4.318 12.7,4.318 20.32,4.318 24.13,4.318 107.95,4.318 119.38,4.318 127,4.318 130.81,4.318 138.43,4.318 146.05,4.318 149.86,4.318 157.48,4.318 168.91,4.318 176.53,4.318 180.34,4.318 187.96,4.318 195.58,4.318 199.39,4.318 207.01,4.318 210.82,4.318 218.44,4.318 229.87,4.318 241.3,4.318 248.92,4.318 256.54,4.318 260.35,4.318 267.97,4.318 271.78,4.318 279.4,4.318 287.02,4.318 290.83,4.318 298.45,4.318 302.26,4.318 309.88,4.318 321.31,4.318 328.93,4.318 340.36,4.318 351.79,4.318 370.84,4.318 378.46,4.318 386.08,4.318 389.89,4.318 393.7,4.318 397.51,4.318 401.32,4.318 405.13,4.318 408.94,4.318 412.75,4.318 416.56,4.318 420.37,4.318 424.18,4.318 427.99,4.318 431.8,4.318 439.42,4.318 443.23,4.318 447.04,4.318 450.85,4.318 462.28,4.318 473.71,4.318 26.035,8.128 29.845,8.128 37.465,8.128 41.275,8.128 48.895,8.128 56.515,8.128 60.325,8.128 67.945,8.128 79.375,8.128 86.995,8.128 90.805,8.128 98.425,8.128 109.855,8.128 117.475,8.128 128.905,8.128 136.525,8.128 140.335,8.128 147.955,8.128 155.575,8.128 159.385,8.128 167.005,8.128 170.815,8.128 178.435,8.128 186.055,8.128 189.865,8.128 197.485,8.128 208.915,8.128 216.535,8.128 227.965,8.128 239.395,8.128 247.015,8.128 250.825,8.128 258.445,8.128 269.875,8.128 277.495,8.128 281.305,8.128 288.925,8.128 296.545,8.128 300.355,8.128 307.975,8.128 311.785,8.128 327.025,8.128 330.835,8.128 338.455,8.128 342.265,8.128 357.505,8.128 361.315,8.128 368.935,8.128 380.365,8.128 384.175,8.128 387.985,8.128 391.795,8.128 395.605,8.128 399.415,8.128 403.225,8.128 410.845,8.128 414.655,8.128 418.465,8.128 422.275,8.128 426.085,8.128 429.895,8.128 437.515,8.128 441.325,8.128 445.135,8.128 448.945,8.128 452.755,8.128 460.375,8.128 464.185,8.128 471.805,8.128 475.615,8.128 382.27,11.938 386.08,11.938 393.7,11.938 397.51,11.938 401.32,11.938 408.94,11.938 412.75,11.938 416.56,11.938 420.37,11.938 424.18,11.938 431.8,11.938 435.61,11.938 439.42,11.938 443.23,11.938 447.04,11.938 450.85,11.938 477.52,11.938 52.705,15.748 151.765,15.748 189.865,15.748 197.485,15.748 201.295,15.748 208.915,15.748 212.725,15.748 216.535,15.748 224.155,15.748 311.785,15.748 315.595,15.748 323.215,15.748 330.835,15.748 334.645,15.748 338.455,15.748 342.265,15.748 353.695,15.748 365.125,15.748 372.745,15.748 376.555,15.748 384.175,15.748 387.985,15.748 391.795,15.748 395.605,15.748 399.415,15.748 403.225,15.748 407.035,15.748 410.845,15.748 414.655,15.748 418.465,15.748 422.275,15.748 429.895,15.748 433.705,15.748 437.515,15.748 441.325,15.748 445.135,15.748 448.945,15.748 452.755,15.748 456.565,15.748 467.995,15.748 475.615,15.748 106.045,23.368 109.855,23.368 117.475,23.368 121.285,23.368 125.095,23.368 132.715,23.368 136.525,23.368 140.335,23.368 144.145,23.368 151.765,23.368 155.575,23.368 167.005,23.368 170.815,23.368 174.625,23.368 178.435,23.368 186.055,23.368 193.675,23.368 197.485,23.368 201.295,23.368 205.105,23.368 208.915,23.368 212.725,23.368 216.535,23.368 220.345,23.368 224.155,23.368 227.965,23.368 231.775,23.368 239.395,23.368 250.825,23.368 258.445,23.368 262.255,23.368 266.065,23.368 269.875,23.368 277.495,23.368 281.305,23.368 288.925,23.368 292.735,23.368 296.545,23.368 300.355,23.368 307.975,23.368 311.785,23.368 315.595,23.368 323.215,23.368 327.025,23.368 330.835,23.368 334.645,23.368 338.455,23.368 342.265,23.368 346.075,23.368 353.695,23.368 357.505,23.368 361.315,23.368 365.125,23.368 368.935,23.368 372.745,23.368 376.555,23.368 384.175,23.368 387.985,23.368 391.795,23.368 395.605,23.368 399.415,23.368 403.225,23.368 407.035,23.368 410.845,23.368 414.655,23.368 422.275,23.368 426.085,23.368 429.895,23.368 433.705,23.368 437.515,23.368 441.325,23.368 445.135,23.368 448.945,23.368 452.755,23.368 456.565,23.368 464.185,23.368 467.995,23.368 471.805,23.368 290.83,27.178 298.45,27.178 302.26,27.178 332.74,27.178 336.55,27.178 347.98,27.178 355.6,27.178 363.22,27.178 367.03,27.178 370.84,27.178 374.65,27.178 382.27,27.178 386.08,27.178 393.7,27.178 397.51,27.178 401.32,27.178 405.13,27.178 408.94,27.178 416.56,27.178 420.37,27.178 424.18,27.178 427.99,27.178 431.8,27.178 443.23,27.178 447.04,27.178 450.85,27.178 454.66,27.178 462.28,27.178 466.09,27.178 469.9,27.178 473.71,27.178 79.375,30.988 86.995,30.988 90.805,30.988 94.615,30.988 98.425,30.988 106.045,30.988 109.855,30.988 113.665,30.988 121.285,30.988 285.115,30.988 441.325,30.988 445.135,30.988 448.945,30.988 452.755,30.988 456.565,30.988 460.375,30.988 464.185,30.988 467.995,30.988 471.805,30.988 1.27,34.798 123.19,34.798 363.22,34.798 367.03,34.798 6.985,38.608 14.605,38.608 22.225,38.608 26.035,38.608 33.655,38.608 45.085,38.608 56.515,38.608 193.675,38.608 205.105,38.608 395.605,38.608 403.225,38.608 407.035,38.608 414.655,38.608 422.275,38.608 426.085,38.608 433.705,38.608 445.135,38.608 452.755,38.608 456.565,38.608 464.185,38.608 12.7,42.418 16.51,42.418 24.13,42.418 35.56,42.418 43.18,42.418 46.99,42.418 54.61,42.418 62.23,42.418 66.04,42.418 73.66,42.418 77.47,42.418 85.09,42.418 92.71,42.418 96.52,42.418 104.14,42.418 115.57,42.418 123.19,42.418 127,42.418 134.62,42.418 142.24,42.418 146.05,42.418 153.67,42.418 165.1,42.418 172.72,42.418 176.53,42.418 184.15,42.418 195.58,42.418 203.2,42.418 207.01,42.418 214.63,42.418 222.25,42.418 226.06,42.418 233.68,42.418 245.11,42.418 252.73,42.418 256.54,42.418 264.16,42.418 275.59,42.418 355.6,42.418 363.22,42.418 367.03,42.418 374.65,42.418 382.27,42.418 386.08,42.418 393.7,42.418 405.13,42.418 412.75,42.418 416.56,42.418 424.18,42.418 435.61,42.418 443.23,42.418 447.04,42.418 454.66,42.418 462.28,42.418 466.09,42.418 473.71,42.418 3.175,46.228
  other v3: 469.011,7.628 458.97,7.671 34.544,10.795 44.577,10.922 315.595,11.684 345.821,11.684 376.555,11.684 64.77,11.811 74.93,11.811 84.963,11.811 184.023,11.811 193.929,11.811 204.216,11.811 214.376,11.811 224.409,11.811 234.442,11.811 244.856,11.811 264.795,11.811 285.115,11.811 305.435,11.811 325.628,11.811 335.788,11.811 355.981,11.811 366.328,11.811 54.737,11.938 104.902,11.938 114.554,11.938 124.46,11.938 134.366,11.938 144.272,11.938 154.178,11.938 164.084,11.938 174.117,11.938 254.762,11.938 274.955,11.938 469.011,11.938 459.062,11.981 94.996,12.065 295.148,12.065 370.459,44.45 10.414,44.577 20.447,44.577 30.48,44.577 40.513,44.577 50.419,44.577 60.452,44.577 70.485,44.577 90.551,44.577 100.457,44.577 110.49,44.577 120.523,44.577 130.429,44.577 140.462,44.577 150.495,44.577 160.528,44.577 170.434,44.577 180.467,44.577 190.5,44.577 200.533,44.577 220.472,44.577 230.505,44.577 240.411,44.577 250.444,44.577 260.477,44.577 270.51,44.577 280.416,44.577 290.449,44.577 300.482,44.577 310.388,44.577 320.421,44.577 330.454,44.577 340.487,44.577 350.393,44.577 360.426,44.577 390.525,44.577 400.431,44.577 440.563,44.577 470.535,44.577 80.518,44.704 380.492,44.704 410.337,44.704 420.37,44.704 430.53,44.704 450.469,44.704 460.502,44.704
LEARN: Q83.1 R83.2 R167.1 | length 3.7
  Top Layer w0.254: R167.1@42.659,6.596 43.612,6.596 R83.2@44.564,6.596 44.564,5.842 44.588,5.818 Q83.1@44.588,4.806
NetD1_1: D1.1 Q1.2 Q2.2 Q3.2 Q4.2 | length 48.4
  Top Layer w0.254: Q1.2@8.702,37.064 Q1.2@8.702,36.764 ; D1.1@18.669,31.428 D1.1@18.102,30.861 16.578,32.385 9.906,32.385 8.702,33.589 Q1.2@8.702,36.764 ; Q2.2@18.698,37.064 18.698,35.843 18.669,35.814 ; Q3.2@28.694,37.064 28.694,35.822 28.702,35.814 ; Q4.2@38.69,37.064 38.69,36.785 37.719,35.814 28.702,35.814 ; Q1.2@8.702,36.764 9.652,35.814 18.669,35.814 ; 18.669,35.814 28.702,35.814
NetD2_1: D2.1 Q5.2 Q6.2 Q7.2 Q8.2 Q9.2 Q10.2 Q11.2 Q12.2 | length 113.6
  Top Layer w0.254: D2.1@26.992,29.083 27.246,28.829 v2(54.483,28.829) ; Q12.2@48.686,37.064 48.686,36.785 49.657,35.814 54.356,35.814 ; v2(54.356,33.782) 54.356,35.814 ; Q11.2@58.682,37.064 58.682,35.822 58.674,35.814 ; Q10.2@68.678,37.064 68.678,35.843 68.707,35.814 ; Q9.2@78.674,37.064 78.674,35.88 78.74,35.814 ; Q8.2@88.67,37.064 88.67,35.838 88.646,35.814 ; Q7.2@98.666,37.064 98.666,35.827 98.679,35.814 ; Q6.2@108.662,37.064 108.662,35.864 108.712,35.814 ; Q5.2@118.658,37.064 118.658,36.743 117.729,35.814 108.712,35.814 ; 54.356,35.814 58.674,35.814 ; 58.674,35.814 68.707,35.814 ; 68.707,35.814 78.74,35.814 ; 78.74,35.814 88.646,35.814 ; 88.646,35.814 98.679,35.814 ; 98.679,35.814 108.712,35.814
  Bottom Layer w0.254: v2(54.356,33.782) 54.483,33.655 v2(54.483,28.829)
NetD3_1: D3.1 Q13.2 Q14.2 Q15.2 Q16.2 Q17.2 Q18.2 Q19.2 Q20.2 | length 194.3
  Top Layer w0.254: D3.1@18.102,27.305 119.131,27.305 Q13.2@128.653,36.828 ; Q13.2@128.653,37.064 Q13.2@128.653,36.828 ; Q14.2@138.649,37.064 138.649,35.722 138.684,35.687 ; Q15.2@148.645,37.064 148.645,35.742 148.59,35.687 ; Q16.2@158.641,37.064 158.641,35.705 158.623,35.687 ; Q17.2@168.637,37.064 168.637,35.706 168.656,35.687 ; Q18.2@178.633,37.064 178.633,35.758 178.562,35.687 ; Q19.2@188.629,37.064 188.629,35.78 188.722,35.687 ; Q20.2@198.625,37.064 198.625,36.827 197.485,35.687 188.722,35.687 ; Q13.2@128.653,36.828 129.794,35.687 138.684,35.687 ; 138.684,35.687 148.59,35.687 ; 148.59,35.687 158.623,35.687 ; 158.623,35.687 168.656,35.687 ; 168.656,35.687 178.562,35.687 ; 178.562,35.687 188.722,35.687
